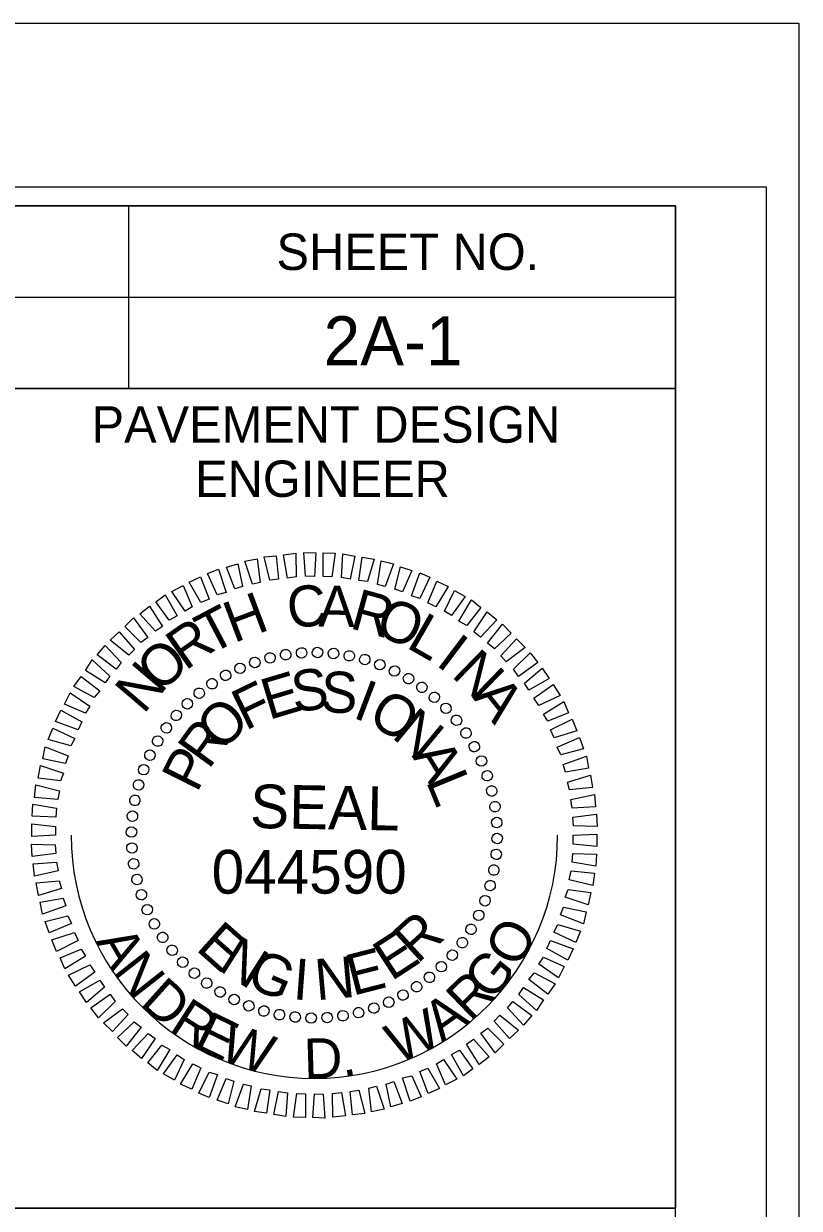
# Model space of a CAD drawing. Extents: x 1497225 to 1499181, y 579958 to 582278.
# Drawn here: x 1498802.9 to 1498909.2, y 582115.4 to 582278 of the extents above; entities that cross this region are included whole.
import ezdxf

# ---------------------------------------------------------------- set-up
doc = ezdxf.new("R2010")
doc.units = 0
for name, color, linetype in [('Scratch_Level_0', 7, 'Continuous'), ('Sheet Cutting Line CELL', 7, 'Continuous'), ('Sheet Data Field CELL', 7, 'Continuous'), ('Sheet Plot Border Inside CELL', 7, 'Continuous'), ('Sheet Plot Border Outside CELL', 7, 'Continuous'), ('Sheet Professional Seal CELL', 7, 'Continuous'), ('Sheet Sticker Exception Certification CELL', 7, 'Continuous'), ('Sheet Typical CELL', 7, 'Continuous')]:
    doc.layers.add(name, color=color, linetype=linetype)

msp = doc.modelspace()

# ---------------------------------------------------------------- linework, layer by layer
at = {"layer": 'Scratch_Level_0'}
msp.add_arc((1498842.73, 582166.59), 33.36, 180, 360, dxfattribs=at)
at = {"layer": 'Sheet Cutting Line CELL'}
msp.add_line((1498909.23, 582277.96), (1497225.23, 582277.96), dxfattribs=at)
at = {"layer": 'Sheet Plot Border Inside CELL'}
msp.add_lwpolyline([(1498904.73, 582255.51), (1497238.23, 582255.51), (1497238.23, 581200.41), (1498904.73, 581200.41)], close=True, dxfattribs=at)
at = {"layer": 'Sheet Plot Border Outside CELL'}
msp.add_lwpolyline([(1498909.23, 582277.96), (1497225.23, 582277.96), (1497225.23, 581177.96), (1498909.23, 581177.96)], close=True, dxfattribs=at)
at = {"layer": 'Sheet Professional Seal CELL'}
for p, q in [((1498834.53, 582190.34), (1498834.53, 582190.34)), ((1498836.63, 582190.94), (1498836.63, 582190.94)), ((1498838.83, 582191.34), (1498838.83, 582191.34)), ((1498840.98, 582191.64), (1498840.98, 582191.64)), ((1498843.18, 582191.69), (1498843.18, 582191.69)), ((1498845.38, 582191.54), (1498845.38, 582191.54)), ((1498847.53, 582191.19), (1498847.53, 582191.19)), ((1498849.63, 582190.74), (1498849.63, 582190.74)), ((1498832.53, 582189.54), (1498832.53, 582189.54)), ((1498851.73, 582190.04), (1498851.73, 582190.04)), ((1498853.73, 582189.14), (1498853.73, 582189.14)), ((1498828.68, 582187.39), (1498828.68, 582187.39)), ((1498830.58, 582188.54), (1498830.58, 582188.54)), ((1498855.68, 582188.14), (1498855.68, 582188.14)), ((1498826.93, 582186.14), (1498826.93, 582186.14)), ((1498857.48, 582186.89), (1498857.48, 582186.89)), ((1498859.23, 582185.54), (1498859.23, 582185.54)), ((1498825.28, 582184.64), (1498825.28, 582184.64)), ((1498860.78, 582184.04), (1498860.78, 582184.04)), ((1498823.78, 582183.09), (1498823.78, 582183.09)), ((1498862.28, 582182.39), (1498862.28, 582182.39)), ((1498822.43, 582181.34), (1498822.43, 582181.34)), ((1498863.53, 582180.64), (1498863.53, 582180.64)), ((1498821.18, 582179.54), (1498821.18, 582179.54)), ((1498820.18, 582177.59), (1498820.18, 582177.59)), ((1498864.68, 582178.74), (1498864.68, 582178.74)), ((1498865.68, 582176.79), (1498865.68, 582176.79)), ((1498819.28, 582175.59), (1498819.28, 582175.59)), ((1498866.48, 582174.79), (1498866.48, 582174.79)), ((1498818.58, 582173.49), (1498818.58, 582173.49)), ((1498867.08, 582172.69), (1498867.08, 582172.69)), ((1498818.13, 582171.39), (1498818.13, 582171.39)), ((1498817.78, 582169.24), (1498817.78, 582169.24)), ((1498867.48, 582170.49), (1498867.48, 582170.49)), ((1498867.78, 582168.34), (1498867.78, 582168.34)), ((1498817.63, 582167.04), (1498817.63, 582167.04)), ((1498842.73, 582166.59), (1498842.73, 582166.59)), ((1498867.83, 582166.14), (1498867.83, 582166.14)), ((1498817.68, 582164.84), (1498817.68, 582164.84)), ((1498867.68, 582163.94), (1498867.68, 582163.94)), ((1498817.98, 582162.69), (1498817.98, 582162.69)), ((1498867.33, 582161.79), (1498867.33, 582161.79)), ((1498818.38, 582160.49), (1498818.38, 582160.49)), ((1498866.88, 582159.69), (1498866.88, 582159.69)), ((1498818.98, 582158.39), (1498818.98, 582158.39)), ((1498819.78, 582156.39), (1498819.78, 582156.39)), ((1498866.18, 582157.59), (1498866.18, 582157.59)), ((1498865.28, 582155.59), (1498865.28, 582155.59)), ((1498820.78, 582154.44), (1498820.78, 582154.44)), ((1498864.28, 582153.64), (1498864.28, 582153.64)), ((1498821.93, 582152.54), (1498821.93, 582152.54)), ((1498863.03, 582151.84), (1498863.03, 582151.84)), ((1498823.18, 582150.79), (1498823.18, 582150.79)), ((1498861.68, 582150.09), (1498861.68, 582150.09)), ((1498824.68, 582149.14), (1498824.68, 582149.14)), ((1498860.18, 582148.54), (1498860.18, 582148.54)), ((1498826.23, 582147.64), (1498826.23, 582147.64)), ((1498858.53, 582147.04), (1498858.53, 582147.04)), ((1498827.98, 582146.29), (1498827.98, 582146.29)), ((1498829.78, 582145.04), (1498829.78, 582145.04)), ((1498856.78, 582145.79), (1498856.78, 582145.79)), ((1498831.73, 582144.04), (1498831.73, 582144.04)), ((1498852.93, 582143.64), (1498852.93, 582143.64)), ((1498854.88, 582144.64), (1498854.88, 582144.64)), ((1498833.73, 582143.14), (1498833.73, 582143.14)), ((1498835.83, 582142.44), (1498835.83, 582142.44)), ((1498837.93, 582141.99), (1498837.93, 582141.99)), ((1498840.08, 582141.64), (1498840.08, 582141.64)), ((1498846.63, 582141.84), (1498846.63, 582141.84)), ((1498848.83, 582142.24), (1498848.83, 582142.24)), ((1498850.93, 582142.84), (1498850.93, 582142.84)), ((1498842.28, 582141.49), (1498842.28, 582141.49)), ((1498844.48, 582141.54), (1498844.48, 582141.54))]:
    msp.add_line(p, q, dxfattribs=at)
for points in [[(1498839.03, 582201.89), (1498838.48, 582205.09), (1498840.18, 582205.29), (1498840.23, 582202.04)], [(1498841.53, 582202.14), (1498841.28, 582205.39), (1498842.93, 582205.34), (1498842.73, 582202.09)], [(1498843.93, 582202.09), (1498843.93, 582205.34), (1498845.58, 582205.29), (1498845.13, 582202.04)], [(1498846.43, 582201.94), (1498846.63, 582205.19), (1498848.28, 582204.89), (1498847.63, 582201.74)], [(1498831.83, 582200.39), (1498830.68, 582203.39), (1498832.23, 582203.84), (1498832.88, 582200.74)], [(1498834.23, 582201.04), (1498833.18, 582204.19), (1498834.88, 582204.54), (1498835.28, 582201.29)], [(1498836.63, 582201.59), (1498835.83, 582204.79), (1498837.48, 582204.94), (1498837.83, 582201.74)], [(1498848.83, 582201.54), (1498849.28, 582204.74), (1498850.93, 582204.49), (1498850.03, 582201.39)], [(1498851.38, 582200.99), (1498851.88, 582204.24), (1498853.58, 582203.84), (1498852.43, 582200.74)], [(1498853.78, 582200.34), (1498854.53, 582203.44), (1498856.08, 582202.94), (1498854.83, 582199.99)], [(1498827.18, 582198.54), (1498825.58, 582201.34), (1498827.13, 582202.04), (1498828.28, 582198.99)], [(1498829.38, 582199.59), (1498828.08, 582202.49), (1498829.58, 582203.09), (1498830.63, 582199.89)], [(1498856.03, 582199.44), (1498857.18, 582202.59), (1498858.58, 582201.99), (1498857.18, 582199.09)], [(1498825.03, 582197.34), (1498823.18, 582200.04), (1498824.73, 582200.84), (1498825.98, 582197.94)], [(1498858.28, 582198.49), (1498859.53, 582201.44), (1498861.08, 582200.74), (1498859.38, 582197.94)], [(1498860.58, 582197.34), (1498861.93, 582200.19), (1498863.43, 582199.34), (1498861.53, 582196.74)], [(1498822.83, 582196.09), (1498820.98, 582198.64), (1498822.28, 582199.59), (1498823.93, 582196.69)], [(1498862.53, 582195.99), (1498864.28, 582198.89), (1498865.58, 582197.84), (1498863.63, 582195.39)], [(1498820.93, 582194.59), (1498818.78, 582196.99), (1498820.13, 582198.04), (1498821.88, 582195.24)], [(1498864.58, 582194.49), (1498866.43, 582197.24), (1498867.73, 582196.14), (1498865.53, 582193.79)], [(1498818.93, 582193.04), (1498816.73, 582195.24), (1498817.93, 582196.44), (1498819.88, 582193.74)], [(1498866.48, 582192.94), (1498868.53, 582195.54), (1498869.73, 582194.34), (1498867.43, 582192.19)], [(1498817.28, 582191.29), (1498814.73, 582193.34), (1498815.98, 582194.49), (1498818.08, 582192.09)], [(1498815.53, 582189.39), (1498812.93, 582191.34), (1498814.03, 582192.64), (1498816.23, 582190.29)], [(1498868.28, 582191.19), (1498870.43, 582193.54), (1498871.63, 582192.34), (1498869.03, 582190.39)], [(1498814.03, 582187.49), (1498811.33, 582189.19), (1498812.28, 582190.64), (1498814.68, 582188.44)], [(1498870.03, 582189.39), (1498872.33, 582191.64), (1498873.38, 582190.29), (1498870.73, 582188.39)], [(1498871.53, 582187.44), (1498873.98, 582189.54), (1498874.93, 582188.09), (1498872.13, 582186.49)], [(1498812.53, 582185.49), (1498809.73, 582186.99), (1498810.73, 582188.39), (1498813.33, 582186.39)], [(1498872.83, 582185.39), (1498875.48, 582187.29), (1498876.43, 582185.79), (1498873.53, 582184.39)], [(1498811.33, 582183.34), (1498808.48, 582184.59), (1498809.23, 582186.14), (1498811.93, 582184.29)], [(1498874.13, 582183.19), (1498876.93, 582184.94), (1498877.58, 582183.39), (1498874.73, 582182.24)], [(1498810.33, 582181.04), (1498807.23, 582182.19), (1498807.98, 582183.74), (1498810.83, 582182.14)], [(1498875.13, 582181.04), (1498878.08, 582182.54), (1498878.73, 582180.94), (1498875.63, 582179.94)], [(1498809.33, 582178.84), (1498806.23, 582179.74), (1498806.88, 582181.29), (1498809.88, 582179.89)], [(1498876.03, 582178.69), (1498879.08, 582179.99), (1498879.63, 582178.44), (1498876.53, 582177.64)], [(1498808.58, 582176.44), (1498805.48, 582177.09), (1498805.83, 582178.74), (1498808.98, 582177.49)], [(1498876.83, 582176.29), (1498880.03, 582177.44), (1498880.33, 582175.79), (1498877.18, 582175.24)], [(1498807.93, 582174.04), (1498804.83, 582174.44), (1498805.18, 582176.14), (1498808.33, 582175.09)], [(1498877.43, 582173.89), (1498880.58, 582174.84), (1498880.88, 582173.14), (1498877.73, 582172.84)], [(1498807.53, 582171.49), (1498804.33, 582171.79), (1498804.53, 582173.49), (1498807.78, 582172.69)], [(1498807.28, 582169.09), (1498804.03, 582169.19), (1498804.13, 582170.84), (1498807.38, 582170.29)], [(1498877.88, 582171.49), (1498881.13, 582172.19), (1498881.28, 582170.49), (1498878.08, 582170.29)], [(1498878.18, 582169.09), (1498881.43, 582169.49), (1498881.53, 582167.79), (1498878.28, 582167.89)], [(1498807.23, 582166.59), (1498803.98, 582166.44), (1498803.98, 582168.14), (1498807.23, 582167.79)], [(1498878.23, 582166.59), (1498881.48, 582166.74), (1498881.48, 582165.04), (1498878.23, 582165.39)], [(1498807.28, 582164.09), (1498804.03, 582163.69), (1498803.93, 582165.39), (1498807.18, 582165.29)], [(1498807.58, 582161.69), (1498804.33, 582160.99), (1498804.18, 582162.69), (1498807.38, 582162.89)], [(1498878.18, 582164.09), (1498881.43, 582163.99), (1498881.33, 582162.34), (1498878.08, 582162.89)], [(1498877.93, 582161.69), (1498881.13, 582161.39), (1498880.93, 582159.69), (1498877.68, 582160.49)], [(1498808.03, 582159.29), (1498804.88, 582158.34), (1498804.58, 582160.04), (1498807.73, 582160.34)], [(1498808.63, 582156.89), (1498805.43, 582155.74), (1498805.13, 582157.39), (1498808.28, 582157.94)], [(1498877.53, 582159.14), (1498880.63, 582158.74), (1498880.28, 582157.04), (1498877.13, 582158.09)], [(1498876.88, 582156.74), (1498879.98, 582156.09), (1498879.63, 582154.44), (1498876.48, 582155.69)], [(1498809.43, 582154.49), (1498806.38, 582153.19), (1498805.83, 582154.74), (1498808.93, 582155.54)], [(1498810.33, 582152.14), (1498807.38, 582150.64), (1498806.73, 582152.24), (1498809.83, 582153.24)], [(1498876.13, 582154.34), (1498879.23, 582153.44), (1498878.58, 582151.89), (1498875.58, 582153.29)], [(1498875.13, 582152.14), (1498878.23, 582150.99), (1498877.48, 582149.44), (1498874.63, 582151.04)], [(1498811.33, 582149.99), (1498808.53, 582148.24), (1498807.88, 582149.79), (1498810.73, 582150.94)], [(1498874.13, 582149.84), (1498876.98, 582148.59), (1498876.23, 582147.04), (1498873.53, 582148.89)], [(1498812.63, 582147.79), (1498809.98, 582145.89), (1498809.03, 582147.39), (1498811.93, 582148.79)], [(1498813.93, 582145.74), (1498811.48, 582143.64), (1498810.53, 582145.09), (1498813.33, 582146.69)], [(1498872.93, 582147.69), (1498875.73, 582146.19), (1498874.73, 582144.79), (1498872.13, 582146.79)], [(1498871.43, 582145.69), (1498874.13, 582143.99), (1498873.18, 582142.54), (1498870.78, 582144.74)], [(1498815.43, 582143.79), (1498813.13, 582141.54), (1498812.08, 582142.89), (1498814.73, 582144.79)], [(1498869.93, 582143.79), (1498872.53, 582141.84), (1498871.43, 582140.54), (1498869.23, 582142.89)], [(1498817.18, 582141.99), (1498815.03, 582139.64), (1498813.83, 582140.84), (1498816.43, 582142.79)], [(1498868.18, 582141.89), (1498870.73, 582139.84), (1498869.48, 582138.69), (1498867.38, 582141.09)], [(1498818.98, 582140.24), (1498816.93, 582137.64), (1498815.73, 582138.84), (1498818.03, 582140.99)], [(1498866.53, 582140.14), (1498868.73, 582137.94), (1498867.53, 582136.74), (1498865.58, 582139.44)], [(1498820.88, 582138.69), (1498819.03, 582135.94), (1498817.73, 582137.04), (1498819.93, 582139.39)], [(1498864.53, 582138.59), (1498866.68, 582136.19), (1498865.33, 582135.14), (1498863.58, 582137.94)], [(1498822.93, 582137.19), (1498821.18, 582134.29), (1498819.88, 582135.34), (1498821.83, 582137.79)], [(1498862.63, 582137.09), (1498864.48, 582134.54), (1498863.18, 582133.59), (1498861.53, 582136.49)], [(1498824.88, 582135.84), (1498823.53, 582132.99), (1498822.03, 582133.84), (1498823.93, 582136.44)], [(1498827.18, 582134.69), (1498825.93, 582131.74), (1498824.38, 582132.44), (1498826.08, 582135.24)], [(1498860.43, 582135.84), (1498862.28, 582133.14), (1498860.73, 582132.34), (1498859.48, 582135.24)], [(1498829.43, 582133.74), (1498828.28, 582130.59), (1498826.88, 582131.19), (1498828.28, 582134.09)], [(1498856.08, 582133.59), (1498857.38, 582130.69), (1498855.88, 582130.09), (1498854.83, 582133.29)], [(1498858.28, 582134.64), (1498859.88, 582131.84), (1498858.33, 582131.14), (1498857.18, 582134.19)], [(1498831.68, 582132.84), (1498830.93, 582129.74), (1498829.38, 582130.24), (1498830.63, 582133.19)], [(1498834.08, 582132.19), (1498833.58, 582128.94), (1498831.88, 582129.34), (1498833.03, 582132.44)], [(1498851.23, 582132.14), (1498852.28, 582128.99), (1498850.58, 582128.64), (1498850.18, 582131.89)], [(1498853.63, 582132.79), (1498854.78, 582129.79), (1498853.23, 582129.34), (1498852.58, 582132.44)], [(1498836.63, 582131.64), (1498836.18, 582128.44), (1498834.53, 582128.69), (1498835.43, 582131.79)], [(1498839.03, 582131.24), (1498838.83, 582127.99), (1498837.18, 582128.29), (1498837.83, 582131.44)], [(1498841.53, 582131.09), (1498841.53, 582127.84), (1498839.88, 582127.89), (1498840.33, 582131.14)], [(1498843.93, 582131.04), (1498844.18, 582127.79), (1498842.53, 582127.84), (1498842.73, 582131.09)], [(1498846.43, 582131.29), (1498846.98, 582128.09), (1498845.28, 582127.89), (1498845.23, 582131.14)], [(1498848.83, 582131.59), (1498849.63, 582128.39), (1498847.98, 582128.24), (1498847.63, 582131.44)]]:
    msp.add_lwpolyline(points, close=True, dxfattribs=at)
for centre, major_axis in [((1498838.8, 582191.36), (-0.113, 0.711)), ((1498840.98, 582191.61), (-0.05, 0.718)), ((1498843.16, 582191.67), (0.013, 0.72)), ((1498845.35, 582191.53), (0.075, 0.716)), ((1498847.51, 582191.21), (0.137, 0.707)), ((1498834.56, 582190.3), (-0.234, 0.681)), ((1498836.66, 582190.93), (-0.174, 0.699)), ((1498849.64, 582190.7), (0.198, 0.692)), ((1498851.71, 582190), (0.258, 0.672)), ((1498830.57, 582188.53), (-0.349, 0.63)), ((1498832.52, 582189.5), (-0.293, 0.658)), ((1498853.72, 582189.13), (0.316, 0.647)), ((1498855.64, 582188.09), (0.371, 0.617)), ((1498828.7, 582187.38), (-0.403, 0.597)), ((1498857.47, 582186.88), (0.423, 0.582)), ((1498826.94, 582186.08), (-0.453, 0.56)), ((1498859.18, 582185.52), (0.472, 0.543)), ((1498823.8, 582183.04), (-0.543, 0.472)), ((1498825.3, 582184.63), (-0.5, 0.518)), ((1498860.77, 582184.01), (0.518, 0.5)), ((1498862.22, 582182.37), (0.56, 0.453)), ((1498822.44, 582181.33), (-0.582, 0.423)), ((1498863.52, 582180.62), (0.597, 0.403)), ((1498821.23, 582179.51), (-0.617, 0.371)), ((1498864.66, 582178.75), (0.63, 0.349)), ((1498820.18, 582177.58), (-0.647, 0.316)), ((1498865.64, 582176.79), (0.658, 0.293)), ((1498819.31, 582175.58), (-0.672, 0.258)), ((1498818.62, 582173.5), (-0.692, 0.198)), ((1498866.44, 582174.76), (0.681, 0.234)), ((1498867.06, 582172.66), (0.699, 0.174)), ((1498818.11, 582171.38), (-0.707, 0.137)), ((1498867.5, 582170.51), (0.711, 0.113)), ((1498817.78, 582169.21), (-0.716, 0.075)), ((1498817.65, 582167.03), (-0.72, 0.013)), ((1498867.74, 582168.34), (0.718, 0.05)), ((1498867.8, 582166.15), (0.72, -0.013)), ((1498817.71, 582164.84), (-0.718, -0.05)), ((1498867.67, 582163.97), (0.716, -0.075)), ((1498817.95, 582162.67), (-0.711, -0.113)), ((1498818.39, 582160.52), (-0.699, -0.174)), ((1498867.34, 582161.81), (0.707, -0.137)), ((1498866.83, 582159.68), (0.692, -0.198)), ((1498819.01, 582158.43), (-0.681, -0.234)), ((1498866.14, 582157.6), (0.672, -0.258)), ((1498819.81, 582156.39), (-0.658, -0.293)), ((1498865.27, 582155.6), (0.647, -0.316)), ((1498820.79, 582154.43), (-0.63, -0.349)), ((1498821.93, 582152.57), (-0.597, -0.403)), ((1498864.22, 582153.67), (0.617, -0.371)), ((1498823.23, 582150.81), (-0.56, -0.453)), ((1498863.02, 582151.85), (0.582, -0.423)), ((1498824.68, 582149.17), (-0.518, -0.5)), ((1498861.65, 582150.14), (0.543, -0.472)), ((1498826.27, 582147.66), (-0.472, -0.543)), ((1498860.15, 582148.55), (0.5, -0.518)), ((1498827.98, 582146.3), (-0.423, -0.582)), ((1498856.75, 582145.8), (0.403, -0.597)), ((1498858.51, 582147.1), (0.453, -0.56)), ((1498829.81, 582145.09), (-0.371, -0.617)), ((1498831.73, 582144.05), (-0.316, -0.647)), ((1498854.88, 582144.66), (0.349, -0.63)), ((1498833.74, 582143.18), (-0.258, -0.672)), ((1498835.81, 582142.48), (-0.198, -0.692)), ((1498850.89, 582142.88), (0.234, -0.681)), ((1498852.93, 582143.68), (0.293, -0.658)), ((1498837.94, 582141.97), (-0.137, -0.707)), ((1498840.1, 582141.65), (-0.075, -0.716)), ((1498842.29, 582141.51), (-0.013, -0.72)), ((1498844.48, 582141.57), (0.05, -0.718)), ((1498846.65, 582141.82), (0.113, -0.711)), ((1498848.79, 582142.26), (0.174, -0.699))]:
    msp.add_ellipse(centre, major_axis=major_axis, ratio=0.999708, dxfattribs=at)
at = {"layer": 'Sheet Sticker Exception Certification CELL'}
msp.add_line((1498692.18, 582115.41), (1498892.22, 582115.41), dxfattribs=at)
at = {"layer": 'Sheet Typical CELL'}
for p, q in [((1498817.23, 582252.91), (1498817.23, 582227.91)), ((1498692.18, 582240.41), (1498892.23, 582240.41))]:
    msp.add_line(p, q, dxfattribs=at)
for points in [[(1498892.23, 582252.96), (1497392.23, 582252.96), (1497392.23, 581202.96), (1498892.23, 581202.96)], [(1498692.18, 582252.96), (1498892.23, 582252.96), (1498892.23, 582227.91), (1498692.18, 582227.91)], [(1498792.23, 582227.91), (1498892.23, 582227.91), (1498892.23, 582115.41), (1498792.23, 582115.41)]]:
    msp.add_lwpolyline(points, close=True, dxfattribs=at)

# ---------------------------------------------------------------- texts
at = {"layer": 'Sheet Data Field CELL'}
msp.add_text('2A-1', height=6.75, dxfattribs=at).set_placement((1498843.99, 582231.06))
at = {"layer": 'Sheet Professional Seal CELL'}
for s, height, rotation, p in [('C', 5.64, 6.2199, (1498839.28, 582194.94)), ('A', 5.64, 359.0203, (1498843.23, 582195.24)), ('R', 5.64, 344.6211, (1498847.43, 582195.04)), ('H', 5.64, 20.6195, (1498831.68, 582192.94)), ('O', 5.64, 337.4212, (1498850.78, 582194.29)), ('T', 5.64, 27.8198, (1498828.43, 582191.29)), ('L', 5.64, 330.2209, (1498855.18, 582192.44)), ('R', 5.64, 35.0205, (1498825.03, 582189.09)), ('I', 5.64, 323.0201, (1498859.23, 582190.04)), ('O', 5.64, 42.2217, (1498821.58, 582185.99)), ('N', 5.64, 315.8189, (1498861.38, 582188.49)), ('N', 5.64, 49.4235, (1498819.28, 582183.09)), ('E', 5.64, 16.6111, (1498836.48, 582182.39)), ('S', 5.64, 7.2556, (1498839.93, 582183.44)), ('S', 5.64, 357.9004, (1498843.53, 582183.49)), ('F', 5.64, 25.967, (1498833.28, 582180.89)), ('I', 5.64, 339.1896, (1498847.83, 582182.79)), ('A', 5.64, 308.6172, (1498864.33, 582185.54)), ('O', 5.64, 329.8335, (1498849.83, 582182.09)), ('O', 5.64, 44.6812, (1498829.98, 582177.94)), ('N', 5.64, 320.4766, (1498853.18, 582180.09)), ('R', 5.64, 54.0397, (1498828.23, 582175.49)), ('P', 5.64, 63.3989, (1498826.63, 582172.29)), ('A', 5.64, 301.7603, (1498856.03, 582177.49)), ('L', 5.64, 292.4008, (1498857.98, 582174.04)), ('SEAL', 5.998, 359, (1498833.88, 582167.59)), ('E', 5.64, 318.2769, (1498826.33, 582150.94)), ('R', 5.64, 42.4814, (1498856.83, 582148.84)), ('O', 5.5, 60.7091, (1498870.66, 582148.19)), ('A', 5.5, 299.9114, (1498812.62, 582152.02)), ('E', 5.64, 33.1241, (1498853.28, 582146.49)), ('N', 5.64, 327.634, (1498829.33, 582148.24)), ('N', 5.5, 308.0972, (1498815, 582147.88)), ('G', 5.64, 336.9902, (1498833.13, 582145.99)), ('N', 5.64, 5.0564, (1498843.03, 582143.94)), ('E', 5.64, 14.4118, (1498847.98, 582144.54)), ('G', 5.5, 50.7774, (1498867.07, 582143.65)), ('I', 5.64, 355.7012, (1498839.68, 582144.09)), ('D', 5.5, 318.0289, (1498818.64, 582143.38)), ('R', 5.5, 43.851, (1498864.12, 582140.88)), ('R', 5.5, 327.1735, (1498822.64, 582139.85)), ('A', 5.5, 35.6652, (1498860.24, 582138.09)), ('E', 5.5, 334.1, (1498826.01, 582137.62)), ('W', 5.5, 24.0591, (1498854.15, 582135.15)), ('W', 5.5, 340.6829, (1498829.44, 582135.89)), ('D', 5.5, 1.7342, (1498841.35, 582133.17)), ('.', 5.5, 10.8788, (1498846.68, 582133.38))]:
    msp.add_text(s, height=height, rotation=rotation, dxfattribs=at).set_placement(p)
msp.add_text('044590', height=5.998, dxfattribs=at).set_placement((1498828.64, 582158.58))
at = {"layer": 'Sheet Typical CELL'}
for s, height, p in [('SHEET NO.', 5, (1498837.53, 582244.16)), ('PAVEMENT DESIGN', 5.0001, (1498812.18, 582220.46)), ('ENGINEER', 5, (1498826.38, 582213.01))]:
    msp.add_text(s, height=height, dxfattribs=at).set_placement(p)

doc.saveas('drawing.dxf')
